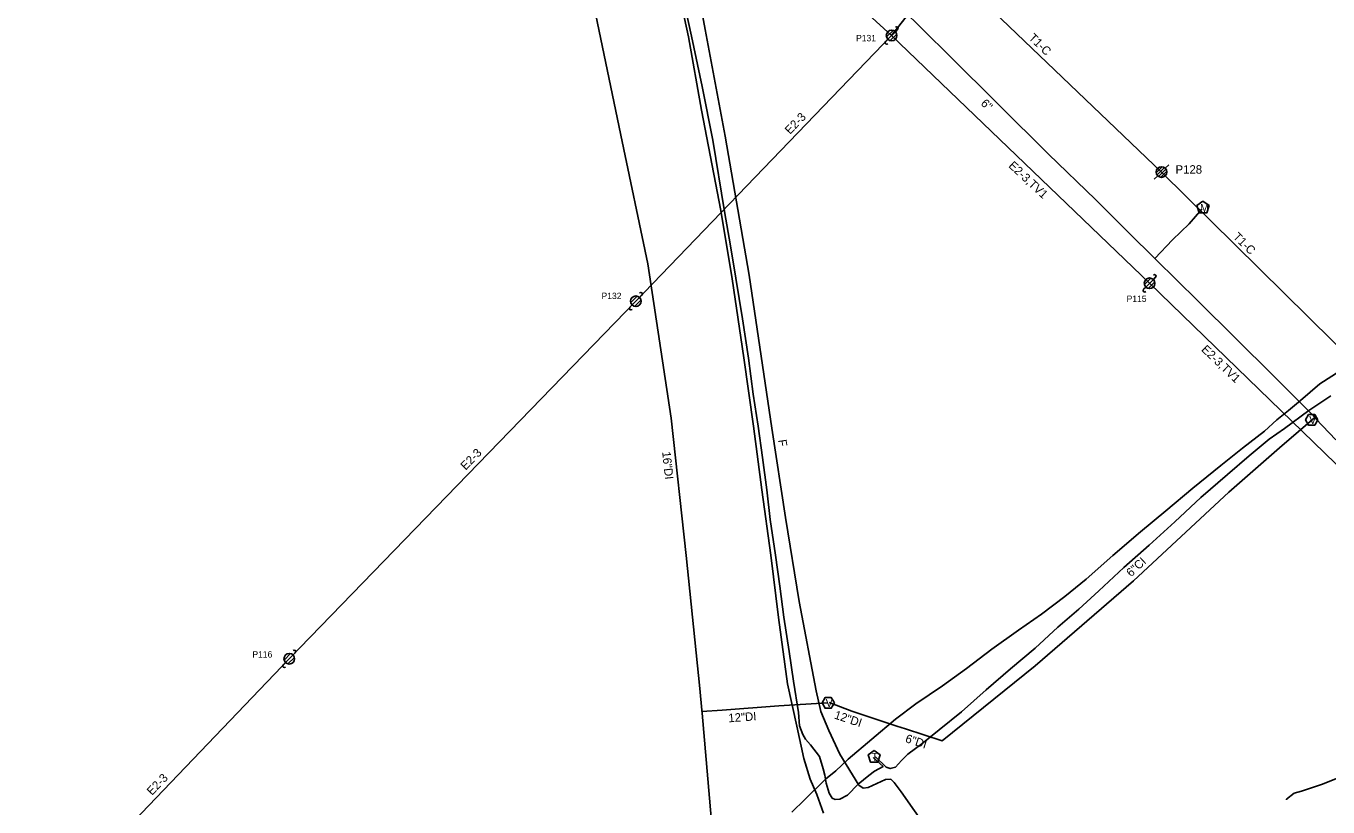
# Model space of a CAD drawing. Extents: x 1741604 to 1825760, y 1164229 to 1194908.
# Drawn here: x 1754813 to 1755425, y 1170142 to 1170510 of the extents above; entities that cross this region are included whole.
import ezdxf

# ---------------------------------------------------------------- set-up
doc = ezdxf.new("R2010")
doc.units = 0
for name, color, linetype in [('RD_EX_SU_H2O', 7, 'Continuous'), ('RD_EX_SU_Ovhd', 7, 'Continuous'), ('RD_EX_SU_Pole', 7, 'Continuous'), ('RD_EX_SU_Telecom', 7, 'Continuous'), ('RD_EX_SU_TX_H2O', 7, 'Continuous'), ('RD_EX_SU_TX_Pole', 7, 'Continuous'), ('RD_EX_SU_TX_Telecom', 7, 'Continuous')]:
    doc.layers.add(name, color=color, linetype=linetype)

# ---------------------------------------------------------------- blocks, each defined once
blk = doc.blocks.new('SUE_PP')
at = {"layer": 'RD_EX_SU_Pole'}
for p, q in [((-2.41, -0.65), (0.65, 2.41)), ((-1.77, -1.77), (1.77, 1.77)), ((-0.65, -2.41), (2.41, 0.65)), ((1.77, 1.77), (2.83, 2.83)), ((-2.83, -2.83), (-1.77, -1.77))]:
    blk.add_line(p, q, dxfattribs=at)
blk.add_circle((0, 0), 2.5, dxfattribs=at)
for centre, start, end in [((2.3, 3.36), 315, 135), ((-2.3, -3.36), 135, 315)]:
    blk.add_arc(centre, 0.75, start, end, dxfattribs=at)
blk = doc.blocks.new('SUE_PTP')
at = {"layer": 'RD_EX_SU_Pole'}
for p, q in [((-2.48, -0.33), (0.33, 2.48)), ((-2.1, -1.36), (1.36, 2.1)), ((-1.4, -2.08), (2.08, 1.4)), ((-0.38, -2.47), (2.47, 0.38)), ((1.77, 1.77), (3.42, 3.42)), ((-3.42, -3.42), (-1.77, -1.77)), ((1.52, -1.99), (1.99, -1.52))]:
    blk.add_line(p, q, dxfattribs=at)
blk.add_circle((0, 0), 2.5, dxfattribs=at)

msp = doc.modelspace()

# ---------------------------------------------------------------- linework, layer by layer
at = {"layer": 'RD_EX_SU_H2O'}
for points in [[(1755042.14, 1170671.77), (1755052.06, 1170641.32), (1755066.9, 1170578.97), (1755079.96, 1170519.29), (1755092.63, 1170458.3), (1755105.45, 1170397.86), (1755116.43, 1170325.12), (1755123.37, 1170260.52), (1755129.9, 1170197.98), (1755130.76, 1170187.84), (1755130.94, 1170186.34), (1755135.98, 1170128.29), (1755137.6, 1170105.08), (1755122.59, 1170093.04)], [(1755224.11, 1170518.52), (1755246.97, 1170496), (1755293.87, 1170449.44), (1755315.82, 1170428.09), (1755331.98, 1170411.89), (1755343.26, 1170400.85), (1755344.34, 1170399.77), (1755363.96, 1170380.46), (1755399.66, 1170345.08), (1755418.36, 1170326.34), (1755419.51, 1170324.82), (1755428.9, 1170315.01)], [(1755343.76, 1170400.34), (1755352.11, 1170409.01), (1755359.99, 1170416.61), (1755365.97, 1170423.44)], [(1755226.62, 1170179), (1755243.72, 1170173.39), (1755287.6, 1170208.74), (1755333.77, 1170248.62), (1755378.52, 1170290.39), (1755402.42, 1170311.28), (1755419.01, 1170325.47)], [(1755130.84, 1170187.19), (1755140.35, 1170187.87), (1755166.97, 1170189.78), (1755189.7, 1170191.28)], [(1755190.62, 1170191.4), (1755201.33, 1170187.41), (1755222.46, 1170180.36), (1755226.62, 1170179)]]:
    msp.add_lwpolyline(points, dxfattribs=at)
for points in [[(1755366.42, 1170427.29), (1755363.52, 1170425.18), (1755364.63, 1170421.77), (1755368.21, 1170421.77), (1755369.32, 1170425.18)], [(1755420.47, 1170324.37), (1755419.03, 1170326.87), (1755416.14, 1170326.87), (1755414.7, 1170324.37), (1755416.14, 1170321.87), (1755419.03, 1170321.87)], [(1755193.09, 1170191.2), (1755191.65, 1170193.7), (1755188.76, 1170193.7), (1755187.32, 1170191.2), (1755188.76, 1170188.7), (1755191.65, 1170188.7)]]:
    msp.add_lwpolyline(points, close=True, dxfattribs=at)
at = {"layer": 'RD_EX_SU_Ovhd'}
for p, q in [((1755019.3, 1170688.81), (1755220.03, 1170505.23)), ((1755220.03, 1170505.23), (1755245.71, 1170538.1)), ((1755245.71, 1170538.1), (1755346.94, 1170440.97)), ((1755099.76, 1170380.2), (1755220.03, 1170505.23)), ((1755220.03, 1170505.23), (1755341.33, 1170388.64)), ((1755346.94, 1170440.97), (1755446.08, 1170343.01)), ((1755341.33, 1170388.64), (1755445.31, 1170287.7)), ((1754936.78, 1170212.01), (1755099.76, 1170380.2)), ((1754812.98, 1170082.79), (1754936.78, 1170212.01))]:
    msp.add_line(p, q, dxfattribs=at)
at = {"layer": 'RD_EX_SU_Pole'}
for p, q in [((1755338.5, 1170385.81), (1755339.56, 1170386.87)), ((1755338.92, 1170388), (1755341.98, 1170391.06)), ((1755339.56, 1170386.87), (1755343.1, 1170390.41)), ((1755340.68, 1170386.23), (1755343.75, 1170389.29)), ((1755343.1, 1170390.41), (1755344.16, 1170391.47)), ((1754934.36, 1170211.36), (1754937.42, 1170214.42)), ((1754938.55, 1170213.78), (1754939.61, 1170214.84)), ((1754933.95, 1170209.18), (1754935.01, 1170210.24)), ((1754935.01, 1170210.24), (1754938.55, 1170213.78)), ((1754936.13, 1170209.59), (1754939.19, 1170212.66))]:
    msp.add_line(p, q, dxfattribs=at)
for centre in [(1755341.33, 1170388.64), (1754936.78, 1170212.01)]:
    msp.add_circle(centre, 2.5, dxfattribs=at)
for centre, start, end in [((1755343.63, 1170392), 315, 135), ((1755339.03, 1170385.28), 135, 315), ((1754939.08, 1170215.37), 315, 135), ((1754934.48, 1170208.65), 135, 315)]:
    msp.add_arc(centre, 0.75, start, end, dxfattribs=at)
at = {"layer": 'RD_EX_SU_Telecom'}
for points in [[(1754967.13, 1170994.05), (1754974.43, 1170968.95), (1754987.04, 1170929.46), (1755004.13, 1170879.16), (1755015.94, 1170845.8), (1755027.84, 1170815.17), (1755036.74, 1170794.1), (1755046.9, 1170772.73), (1755058.13, 1170753.54), (1755068.96, 1170735.75), (1755072.88, 1170726.57), (1755079.23, 1170717.91), (1755082.2, 1170712.4), (1755082.99, 1170707.43), (1755087.24, 1170669.18), (1755089.17, 1170658.27), (1755093.84, 1170646.29), (1755105.7, 1170595.36), (1755111, 1170568.73), (1755116.38, 1170542.14), (1755124.51, 1170504.65), (1755130.68, 1170470.03), (1755139.68, 1170422.81)], [(1755125.66, 1170544.73), (1755132.36, 1170508.03), (1755141.69, 1170457.83), (1755153, 1170392.52), (1755163.7, 1170320.44), (1755170.12, 1170278.41), (1755176.51, 1170238.92), (1755184.51, 1170196.9), (1755186.76, 1170187.26), (1755190.44, 1170178.21), (1755195.62, 1170167.16), (1755204.6, 1170152.57), (1755206.63, 1170151.08), (1755209.01, 1170151.38), (1755217.1, 1170155.17), (1755219.59, 1170155.29), (1755221.22, 1170153.85), (1755224.5, 1170149.37), (1755248.56, 1170115.21)], [(1755121.12, 1170527.09), (1755125.84, 1170504.97), (1755130.97, 1170481.16), (1755135.88, 1170455.94), (1755141.43, 1170422.44), (1755144.22, 1170406.29), (1755146.82, 1170391.01), (1755149.83, 1170371.93), (1755152.73, 1170353.44), (1755154.96, 1170336.5), (1755157.29, 1170321.48), (1755159.28, 1170306.68), (1755161.27, 1170291.42), (1755162.95, 1170277.45), (1755165.43, 1170260.77), (1755167.47, 1170246.18), (1755169.27, 1170231.62), (1755171.82, 1170215.4), (1755173.85, 1170201.42), (1755176.25, 1170186.65), (1755176.66, 1170180.43), (1755178.21, 1170176.34), (1755179.46, 1170174.23), (1755181.82, 1170171.58), (1755186.11, 1170166.08), (1755187.8, 1170160.21), (1755188.57, 1170157.17), (1755189.25, 1170153.5), (1755190.71, 1170148.72), (1755192.1, 1170146.47), (1755193.46, 1170145.74), (1755195.73, 1170145.93), (1755199.2, 1170147.81), (1755204.23, 1170153.01), (1755209.26, 1170157.08), (1755212.02, 1170159.17), (1755216.03, 1170161.33), (1755211.36, 1170165.61)], [(1755139.68, 1170422.81), (1755145, 1170390.8), (1755150.56, 1170353.51), (1755155, 1170321.36), (1755158.99, 1170291.53), (1755163.21, 1170260.78), (1755166.78, 1170231.39), (1755171.04, 1170200.27), (1755175.51, 1170180.35), (1755178.79, 1170165.14), (1755181.73, 1170155.39), (1755184.81, 1170148.09), (1755188.05, 1170139.31)], [(1755173.13, 1170139.77), (1755179.2, 1170145.85), (1755188.93, 1170155.36), (1755193.85, 1170159.25), (1755199.54, 1170164.75), (1755221.91, 1170183.63), (1755231.43, 1170190.76), (1755243.94, 1170199.24), (1755255.26, 1170207.46), (1755267.22, 1170216.55), (1755279.64, 1170225.39), (1755290.46, 1170233.01), (1755301.55, 1170241.28), (1755311.45, 1170249.41), (1755324.03, 1170260.54), (1755337.03, 1170271.76), (1755349.03, 1170281.63), (1755361.72, 1170292.23), (1755374.77, 1170302.94), (1755384.99, 1170311.09), (1755395.34, 1170319.13), (1755401.11, 1170324.38), (1755406.6, 1170328.78), (1755412.26, 1170333.43), (1755421.33, 1170341.29), (1755431, 1170347.4)], [(1755212.37, 1170165.85), (1755217.4, 1170161), (1755219.36, 1170160.36), (1755221.82, 1170160.97), (1755224.64, 1170164.07), (1755227.68, 1170167.05), (1755234.25, 1170172.01), (1755242.34, 1170178.49), (1755252.88, 1170186.96), (1755264.52, 1170197.36), (1755275.93, 1170207.26), (1755287.45, 1170216.94), (1755298.21, 1170226.89), (1755308.1, 1170235.27), (1755317.43, 1170243.99), (1755329.17, 1170254.86), (1755341.18, 1170265.41), (1755353.16, 1170276.42), (1755365.37, 1170287.84), (1755377.96, 1170298.71), (1755388.14, 1170307.51), (1755397.56, 1170315.38), (1755404.79, 1170320.34), (1755416.15, 1170328.72), (1755426.62, 1170335.77)], [(1755405.67, 1170145.67), (1755405.69, 1170145.88), (1755409.29, 1170148.79), (1755412.83, 1170149.69), (1755422.25, 1170152.84), (1755435.11, 1170158.07), (1755450.17, 1170159.81), (1755465.33, 1170159.04), (1755479.15, 1170155.53), (1755491.77, 1170153.46), (1755510.49, 1170150.43), (1755540.94, 1170157.22), (1755551.15, 1170161.61), (1755560.81, 1170162.66), (1755565.75, 1170161.22), (1755573.61, 1170156.42), (1755577.72, 1170155.21)]]:
    msp.add_lwpolyline(points, dxfattribs=at)
msp.add_lwpolyline([(1755211.81, 1170168.84), (1755208.95, 1170166.77), (1755210.04, 1170163.41), (1755213.57, 1170163.41), (1755214.66, 1170166.77)], close=True, dxfattribs=at)

# ---------------------------------------------------------------- block references
at = {"layer": 'RD_EX_SU_Pole'}
for p in [(1755220.03, 1170505.23), (1755099.76, 1170380.2)]:
    msp.add_blockref('SUE_PP', p, dxfattribs=at)
at = {"layer": 'RD_EX_SU_Telecom'}
msp.add_blockref('SUE_PTP', (1755346.94, 1170440.97), dxfattribs=at)

# ---------------------------------------------------------------- texts
at = {"layer": 'RD_EX_SU_H2O'}
for s, p in [('M', (1755365.05, 1170422.24)), ('V', (1755416.38, 1170322.5)), ('V', (1755189, 1170189.32))]:
    msp.add_text(s, height=3.75, dxfattribs=at).set_placement(p)
at = {"layer": 'RD_EX_SU_Ovhd'}
for s, rotation, p in [('T1-C', 315.60508, (1755284.17, 1170503.79)), ('E2-3', 46.11308, (1755172.25, 1170458.44)), ('E2-3,TV1', 316.96676, (1755274.71, 1170443.58)), ('T1-C', 315.60508, (1755380.26, 1170410.13)), ('E2-3,TV1', 316.23715, (1755365.39, 1170357.13)), ('E2-3', 45.89982, (1755019.73, 1170300.48)), ('E2-3', 46.2276, (1754872.2, 1170147.49))]:
    msp.add_text(s, height=4, rotation=rotation, dxfattribs=at).set_placement(p)
at = {"layer": 'RD_EX_SU_Telecom'}
msp.add_text('T', height=3.75, dxfattribs=at).set_placement((1755210.55, 1170163.96))
at = {"layer": 'RD_EX_SU_TX_H2O'}
for s, rotation, p in [('6"', 315.20666, (1755261.67, 1170472.95)), ('16"DI', 276.13002, (1755112.1, 1170309.3)), ('6"CI', 43.02026, (1755332.61, 1170250.28)), ('12"DI', 4.09218, (1755143.38, 1170182.08)), ('12"DI', 341.54618, (1755192.72, 1170183.96)), ('6"DI', 341.85989, (1755226.15, 1170172.84))]:
    msp.add_text(s, height=4, rotation=rotation, dxfattribs=at).set_placement(p)
at = {"layer": 'RD_EX_SU_TX_Pole'}
for s, height, p in [('P131', 3, (1755203.31, 1170502.5)), ('P128', 4, (1755353.53, 1170440.19)), ('P132', 3, (1755083.62, 1170381.21)), ('P115', 3, (1755330.54, 1170379.88)), ('P116', 3, (1754919.42, 1170212.57))]:
    msp.add_text(s, height=height, dxfattribs=at).set_placement(p)
at = {"layer": 'RD_EX_SU_TX_Telecom'}
msp.add_text('F', height=4, rotation=278.68117, dxfattribs=at).set_placement((1755166.57, 1170314.87))

doc.saveas('drawing.dxf')
